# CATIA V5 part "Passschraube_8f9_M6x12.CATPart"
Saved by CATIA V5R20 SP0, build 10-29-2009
Part number: Passschraube_8f9_M6x12
Bounding box of the stored display mesh (mm): x -6.5 to 6.5, y -6.5 to 6.5, z -28.5 to 0
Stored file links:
  C:\Users\Andi\Desktop\Plasma\Passschraube_8f9_M6x12.CATPart
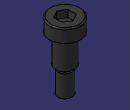
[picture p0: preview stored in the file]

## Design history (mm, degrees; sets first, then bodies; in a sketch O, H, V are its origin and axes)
Body1 (main body)
  Sketch1 on zx-plane, origin (0, 0, 0), H (-1, 0, 0), V (0, 0, 1)
    axis line L1 (0, 20.0273) -> (0, -25.5974)
    point P1 (0, 20.0273)
    line L2 (0, 0) -> (6.5, 0)
    line L3 (6.5, 0) -> (6.5, -5.5)
    line L4 (6.5, -5.5) -> (4, -5.5)
    line L5 (4, -5.5) -> (4, -17.5)
    line L6 (4, -17.5) -> (2.25, -17.5)
    line L7 (2.25, -17.5) -> (2.25, -19)
    line L8 (2.25, -19) -> (3, -19)
    line L9 (3, -19) -> (3, -28.5)
    line L10 (3, -28.5) -> (0, -28.5)
    point P11 (0, -28.5)
    length L5 = 12
    distance L6 L10 = 11
    distance L9 L1 = 3
    distance L5 L1 = 4
    length L3 = 5.5
    length L2 = 6.5
    length L7 = 1.5
    length L6 = 1.75
    coincidence: P1 V, P11 L1
    vertical: L1 V, L3 V, L5 V, L7 V, L9 V
    horizontal: L2 H, L4 H, L6 H, L8 H, L10 H
  Shaft1: profile Sketch1, axis Sketch1.L1, angle 360
  Chamfer1: length 0.5, angle 45, on edge [face of Shaft1 | face of Shaft1]
  Fillet1: radius 0.5, on edge [face of Shaft1 | face of Shaft1]
  Sketch2 on face of Shaft1, origin (0, 0, 0), H (1, 0, 0), V (0, 1, 0)
    point P1 (3, -1.7321)
    point P2 (3, 1.7321)
    point P3 (0, 3.4641)
    point P4 (-3, 1.7321)
    point P5 (-3, -1.7321)
    point P6 (0, -3.4641)
    line L1 (3, -1.7321) -> (3, 1.7321)
    line L2 (3, 1.7321) -> (0, 3.4641)
    line L3 (0, 3.4641) -> (-3, 1.7321)
    line L4 (-3, 1.7321) -> (-3, -1.7321)
    line L5 (-3, -1.7321) -> (0, -3.4641)
    line L6 (0, -3.4641) -> (3, -1.7321)
    construction line L7 (0, 0) -> (1.25, 0)
    construction circle A1 centre (0, 0) radius 3.4641
    construction arc A2 centre (-3, -1.7321) radius 3.4641 from (-3, 1.7321) to (0, -3.4641) cw
    construction arc A3 centre (3, 1.7321) radius 3.4641 from (0, 3.4641) to (3, -1.7321) ccw
    distance L4 L1 = 6
    horizontal: L7 H
    coincidence: A1 P1, A1 P2, A1 P3, A1 P4, A1 P5, A1 P6, A2 O, A3 O
    vertical: L1 V
  Pocket1: profile Sketch2, direction (0, 0, -1), length 3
